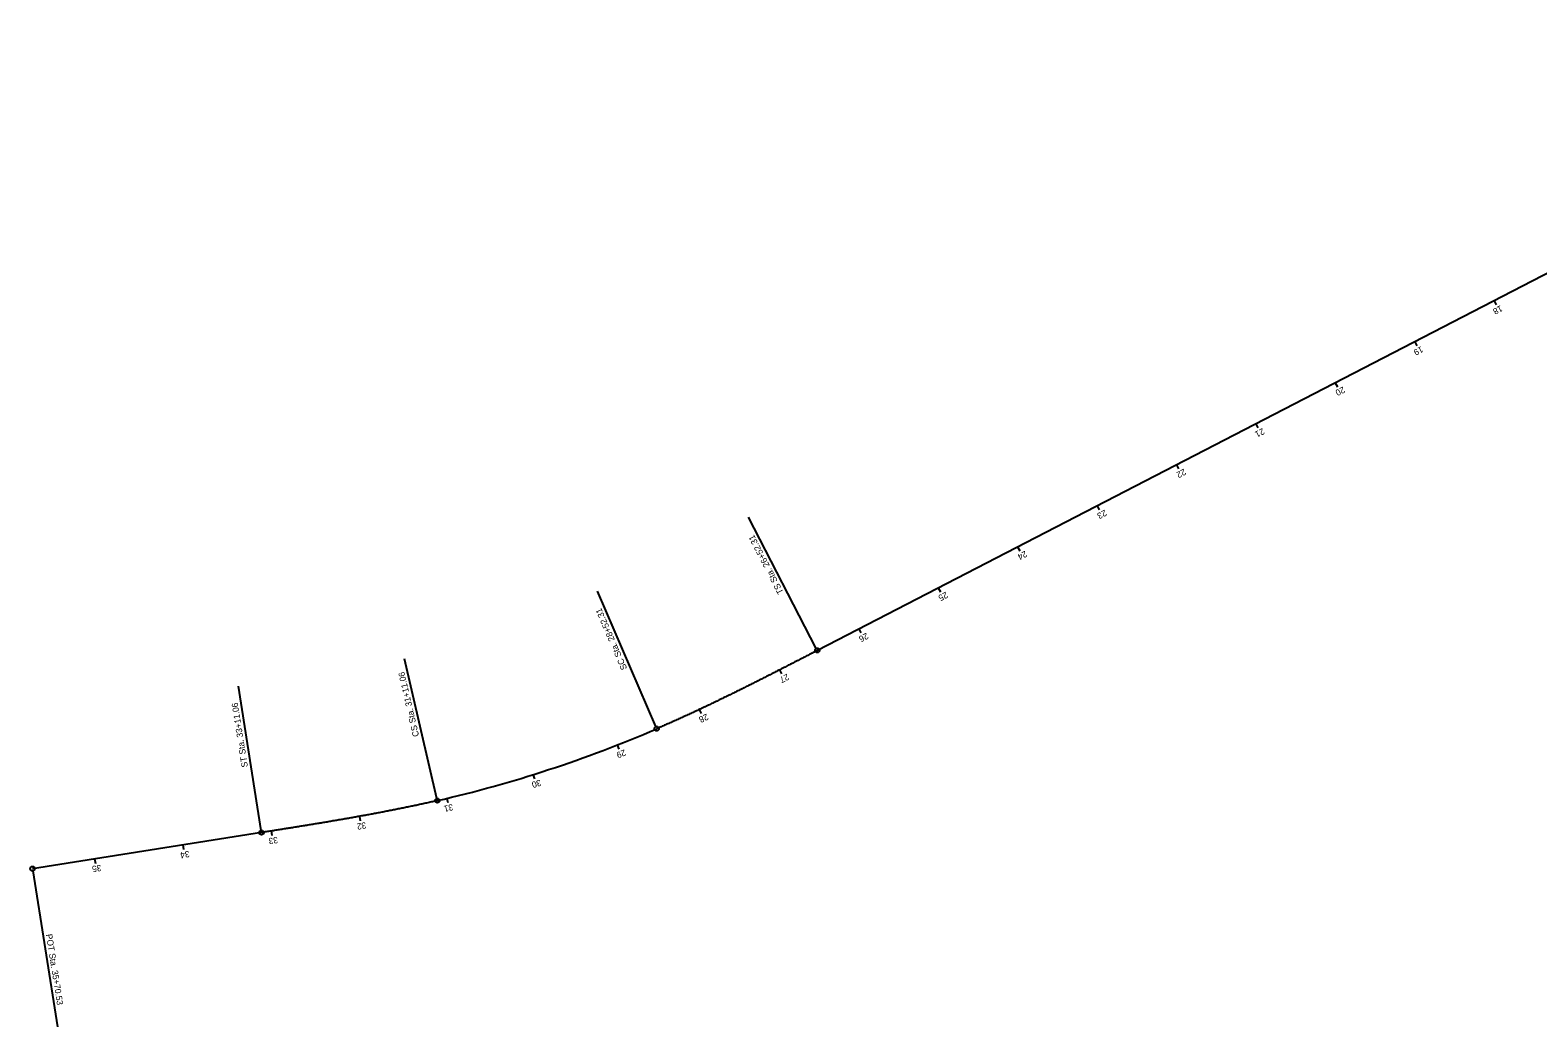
# Model space of a CAD drawing. Extents: x 21904 to 36537, y 12187 to 32963.
# Drawn here: x 22144 to 23831, y 27336 to 28452 of the extents above; entities that cross this region are included whole.
import ezdxf

# ---------------------------------------------------------------- set-up
doc = ezdxf.new("R2010")
doc.units = 0
doc.layers.add('GE_X_CL_50', color=7, linetype='Continuous')

msp = doc.modelspace()

# ---------------------------------------------------------------- linework, layer by layer
at = {"layer": 'GE_X_CL_50'}
for p, q in [((24367.9, 28451.7), (23024.4, 27757.7)), ((23781.6, 28148.9), (23783.9, 28144.4)), ((23692.8, 28103), (23695.1, 28098.5)), ((23603.9, 28057.1), (23606.2, 28052.6)), ((23515.1, 28011.2), (23517.4, 28006.7)), ((23426.2, 27965.3), (23428.5, 27960.8)), ((23023.2, 27759.9), (22947.3, 27906.9)), ((23337.4, 27919.4), (23339.7, 27914.9)), ((23248.5, 27873.5), (23250.8, 27869.1)), ((22843.6, 27672.4), (22778.2, 27824.1)), ((23159.7, 27827.6), (23162, 27823.2)), ((23070.8, 27781.7), (23073.1, 27777.3)), ((22598.5, 27592), (22562.5, 27748.3)), ((22982, 27735.9), (22984.3, 27731.4)), ((22402, 27556.3), (22376.5, 27717.6)), ((22892.3, 27691.6), (22894.4, 27687.1)), ((22800.5, 27651.9), (22802.4, 27647.3)), ((22706.2, 27618.7), (22707.7, 27613.9)), ((22609.9, 27592.1), (22611, 27587.3)), ((22511.9, 27571.9), (22512.8, 27567)), ((22402.4, 27553.8), (22146.1, 27513.4)), ((22413.3, 27555.6), (22414.1, 27550.6)), ((22314.5, 27540), (22315.3, 27535)), ((22215.7, 27524.4), (22216.5, 27519.4)), ((22146.4, 27510.9), (22174, 27336.4))]:
    msp.add_line(p, q, dxfattribs=at)
for centre in [(23024.4, 27757.7), (22844.6, 27670.1), (22599.1, 27589.6), (22402.4, 27553.8), (22146.1, 27513.4)]:
    msp.add_circle(centre, 2.5, dxfattribs=at)
msp.add_arc((22277.6, 28985.4), 1432.4, 282.9708, 293.3208, dxfattribs=at)
for points in [[(23024.4, 27757.7), (23022, 27756.4), (23019.6, 27755.2), (23017.2, 27754), (23014.8, 27752.7), (23012.4, 27751.5), (23010, 27750.2), (23007.6, 27749), (23005.2, 27747.8), (23002.8, 27746.5), (23000.4, 27745.3), (22998, 27744.1), (22995.6, 27742.8), (22993.1, 27741.6), (22990.7, 27740.4), (22988.3, 27739.1), (22985.9, 27737.9), (22983.5, 27736.7), (22981.1, 27735.4), (22978.7, 27734.2), (22976.3, 27733), (22973.9, 27731.7), (22971.5, 27730.5), (22969.1, 27729.3), (22966.7, 27728.1), (22964.3, 27726.8), (22961.9, 27725.6), (22959.4, 27724.4), (22957, 27723.2), (22954.6, 27722), (22952.2, 27720.8), (22949.8, 27719.5), (22947.4, 27718.3), (22944.9, 27717.1), (22942.5, 27715.9), (22940.1, 27714.7), (22937.7, 27713.5), (22935.3, 27712.3), (22932.8, 27711.1), (22930.4, 27709.9), (22928, 27708.7), (22925.6, 27707.5), (22923.1, 27706.3), (22920.7, 27705.2), (22918.3, 27704), (22915.8, 27702.8), (22913.4, 27701.6), (22911, 27700.5), (22908.5, 27699.3), (22906.1, 27698.1), (22903.7, 27696.9), (22901.2, 27695.8), (22898.8, 27694.6), (22896.3, 27693.5), (22893.9, 27692.3), (22891.5, 27691.2), (22889, 27690), (22886.6, 27688.9), (22884.1, 27687.7), (22881.6, 27686.6), (22879.2, 27685.5), (22876.7, 27684.4), (22874.3, 27683.2), (22871.8, 27682.1), (22869.4, 27681), (22866.9, 27679.9), (22864.4, 27678.8), (22862, 27677.7), (22859.5, 27676.6), (22857, 27675.5), (22854.5, 27674.4), (22852.1, 27673.3), (22849.6, 27672.2), (22847.1, 27671.1), (22844.6, 27670.1)], [(22599.1, 27589.6), (22596.5, 27589), (22593.8, 27588.4), (22591.2, 27587.8), (22588.5, 27587.2), (22585.9, 27586.6), (22583.3, 27586), (22580.6, 27585.5), (22578, 27584.9), (22575.3, 27584.3), (22572.7, 27583.8), (22570.1, 27583.2), (22567.4, 27582.7), (22564.8, 27582.1), (22562.1, 27581.6), (22559.5, 27581), (22556.8, 27580.5), (22554.2, 27580), (22551.5, 27579.4), (22548.9, 27578.9), (22546.2, 27578.4), (22543.6, 27577.9), (22540.9, 27577.3), (22538.3, 27576.8), (22535.6, 27576.3), (22532.9, 27575.8), (22530.3, 27575.3), (22527.6, 27574.8), (22525, 27574.3), (22522.3, 27573.8), (22519.7, 27573.3), (22517, 27572.9), (22514.3, 27572.4), (22511.7, 27571.9), (22509, 27571.4), (22506.4, 27570.9), (22503.7, 27570.5), (22501, 27570), (22498.4, 27569.5), (22495.7, 27569.1), (22493.1, 27568.6), (22490.4, 27568.1), (22487.7, 27567.7), (22485.1, 27567.2), (22482.4, 27566.8), (22479.7, 27566.3), (22477.1, 27565.9), (22474.4, 27565.4), (22471.7, 27565), (22469.1, 27564.5), (22466.4, 27564.1), (22463.7, 27563.7), (22461.1, 27563.2), (22458.4, 27562.8), (22455.7, 27562.4), (22453.1, 27561.9), (22450.4, 27561.5), (22447.7, 27561.1), (22445.1, 27560.6), (22442.4, 27560.2), (22439.7, 27559.8), (22437.1, 27559.3), (22434.4, 27558.9), (22431.7, 27558.5), (22429.1, 27558.1), (22426.4, 27557.6), (22423.7, 27557.2), (22421, 27556.8), (22418.4, 27556.4), (22415.7, 27555.9), (22413, 27555.5), (22410.4, 27555.1), (22407.7, 27554.7), (22405, 27554.3), (22402.4, 27553.8)]]:
    msp.add_spline(points, degree=3, dxfattribs=at)

# ---------------------------------------------------------------- texts
for s, rotation, p in [('18', 207.3208, (23788.8, 28144.1)), ('19', 207.3208, (23700, 28098.3)), ('20', 207.3208, (23612.5, 28053.1)), ('21', 207.3208, (23522.5, 28006.6)), ('22', 207.3208, (23434.6, 27961.2)), ('23', 207.3208, (23345.9, 27915.3)), ('TS Sta. 26+52.31', 117.3208, (22986.8, 27822.7)), ('24', 207.3208, (23256.9, 27869.4)), ('25', 207.3208, (23168.2, 27823.5)), ('SC Sta. 28+52.31', 113.3208, (22811.7, 27737.6)), ('26', 207.3208, (23079.3, 27777.6)), ('CS Sta. 31+11.06', 102.9708, (22578.8, 27661.9)), ('27', 207.0934, (22990.6, 27731.8)), ('ST Sta. 33+11.06', 98.9708, (22387.2, 27627.4)), ('28', 205.1396, (22900.5, 27687.1)), ('29', 201.4132, (22808.5, 27647)), ('30', 197.4132, (22714.1, 27613.3)), ('31', 193.4132, (22616, 27585.9)), ('33', 188.9831, (22420.2, 27549.1)), ('32', 190.2043, (22518.9, 27565.6)), ('34', 188.9708, (22321.3, 27533.4)), ('35', 188.9708, (22222.6, 27517.9)), ('POT Sta. 35+70.53', 278.9708, (22161.2, 27439.8))]:
    msp.add_text(s, height=7, rotation=rotation, dxfattribs=at).set_placement(p)

doc.saveas('drawing.dxf')
